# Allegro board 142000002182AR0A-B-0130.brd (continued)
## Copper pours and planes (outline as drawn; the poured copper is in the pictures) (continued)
VCC_12P_FAN4_IN on TOP (solid shape): 240.03,42.42 240.03,35.33 239.07,34.36 237.32,32.61 232.77,32.61 231.22,34.16 231.13,34.16 231.12,34.17 230.35,34.17 230.32,34.17 230.28,34.16 229.93,34.16 229.93,35.81 229.93,36.26 230.2,36.53 231.75,36.53 231.75,35.72 232.82,35.72 232.82,35.73 236.5,35.73 236.75,35.97 236.75,38.46 237.96,38.46 237.96,39.52 236.75,39.52 236.75,39.88 236.92,40.05 236.92,41.85 237.74,42.67 239.78,42.67
VCC_12P_FAN4_IN on BOTTOM: 237.44,55.32 237.52,55.4 238.89,55.4 238.99,55.3 238.99,47.32 239.32,46.99 239.32,42.24 239.95,41.61 239.95,38.93 239.57,38.55 236.48,38.55 235.79,39.24 235.79,44.3 236.7,45.21 236.7,46.66 237.44,47.4
VCC_12P_FAN4_OUT on TOP (solid shape): 243.75,45.48 244.23,45.48 244.52,45.39 244.82,45.48 245.63,45.48 245.97,45.14 245.97,43.46 245.99,43.44 245.99,43.34 246.09,43.34 247.04,42.39 247.04,37.82 245.49,36.27 245.49,36.19 245.48,36.18 245.48,35.41 245.48,35.37 245.49,35.33 245.49,34.99 243.84,34.99 243.84,34.99 243.04,34.99 242.77,35.26 242.77,36.8 243.55,36.8 243.55,37.87 243.21,37.87 243.21,38.05 243.33,38.18 243.79,38.18 243.84,38.23 243.84,39.5 243.84,40.26 243.84,41.53 243.84,41.58 243.54,41.88 243.55,41.88 243.55,42.95 241.59,42.95 241.59,42.93 241.07,42.93 240.49,43.51 240.49,45.49 240.89,45.9 243.33,45.9
VCC_12P_FAN4_OUT on BOTTOM: 239.7,43.35 239.7,47.01 239.99,47.29 239.99,55.23 240.15,55.4 241.43,55.4 241.52,55.3 241.52,47.32 242.27,46.58 242.27,45.85 243.1,45.01 244.9,45.01 245.51,44.41 245.51,41.52 244.94,40.95 242.1,40.95
VCC_12P_FAN5_IN on TOP: 302.96,38.57 304.88,38.57 306.36,40.05 308.38,40.05 308.71,39.72 308.71,37.72 306.52,35.53 306.52,32.49 305.79,31.77 305.79,31.5 305.71,31.42 305.71,30.21 305.59,30.08 303.96,30.08 303.94,30.1 302.56,30.1 302.1,30.55 302.1,32.07 302.3,32.27 303,32.27 303,37.36 303.09,37.45 303.09,38.44
VCC_12P_FAN5_IN on BOTTOM: 306.35,55.32 306.43,55.39 307.8,55.39 307.9,55.29 307.9,47.32 308.23,46.99 308.23,42.24 308.87,41.6 308.87,38.93 308.48,38.55 305.39,38.55 304.7,39.24 304.7,44.29 305.61,45.21 305.61,46.66 306.35,47.39
VCC_12P_FAN5_OUT on TOP: 313.79,31.31 313.79,30.03 313.55,29.78 312.41,29.78 311.87,30.32 311.87,38.18 311.88,38.19 309.7,40.38 309.7,42.69 310.12,43.11 314.09,43.11 314.49,42.71 314.49,40.95 315.7,39.74 315.7,32.56 314.64,31.49 313.97,31.49
VCC_12P_FAN5_OUT on BOTTOM: 308.61,43.34 308.61,47 308.9,47.29 308.9,55.23 309.06,55.39 310.34,55.39 310.43,55.3 310.43,47.32 311.18,46.57 311.18,45.84 312.01,45.01 313.81,45.01 314.42,44.4 314.42,41.52 313.85,40.95 311.01,40.95
VCC_12P_FAN6_IN on TOP: 371.73,39.24 373.38,39.24 374.65,40.51 375.54,40.51 375.92,40.13 375.92,35.69 374.22,33.99 374.22,32.46 374.14,32.38 371.73,32.38 371.09,33.02 371.09,33.27 371.13,33.3 371.66,33.3 371.73,33.37
VCC_12P_FAN6_IN on BOTTOM: 375.25,54.8 375.33,54.87 376.7,54.87 376.8,54.77 376.8,46.8 377.13,46.47 377.13,39.77 376.1,38.73 373.73,38.73 373.6,38.86 373.6,43.77 374.51,44.69 374.51,46.14 375.25,46.87
VCC_12P_FAN6_OUT on TOP: 380.75,43.31 383.03,43.31 383.54,42.8 383.54,41.78 385.95,39.37 385.95,36.7 384.05,34.8 384.05,33.78 383.79,33.53 382.27,33.53 381.38,34.42 381.38,40.39 380.87,40.89 380.49,40.89 380.24,41.15 380.24,42.8
VCC_12P_FAN6_OUT on BOTTOM: 377.51,42.82 377.51,46.48 377.8,46.77 377.8,54.71 377.96,54.87 379.24,54.87 379.33,54.78 379.33,46.8 380.08,46.05 380.08,45.32 380.91,44.49 382.71,44.49 383.32,43.88 383.32,41.71 383.02,41.41 378.92,41.41
VCC_CL_FAN1F on TOP (solid shape): 41.15,30 41.15,29.69 41.14,29.65 41.14,29.61 41.14,28.98 41.15,28.97 41.15,28.85 41.78,28.23 41.81,28.17 41.81,26.7 41.66,26.54 38.71,26.54 38.69,26.53 38.26,26.53 38.15,26.63 38.15,29.78 38.4,30.02 41.12,30.02
VCC_CL_FAN1R on TOP: 31.09,30.02 31.11,30 31.11,28.85 31.78,28.19 31.78,26.7 31.62,26.54 28.68,26.54 28.66,26.53 28.23,26.53 28.12,26.63 28.12,29.78 28.36,30.02
VCC_CL_FAN2F on TOP (solid shape): 108.46,31.9 108.46,31.6 108.45,31.56 108.45,31.52 108.45,30.88 108.46,30.87 108.46,30.76 109.09,30.13 109.12,30.08 109.12,28.26 108.78,27.92 105.7,27.92 105.46,28.16 105.46,31.68 105.71,31.93 108.43,31.93
VCC_CL_FAN2R on TOP (solid shape): 90.73,37.29 90.73,34.57 90.7,34.54 90.4,34.54 90.36,34.55 90.32,34.55 89.68,34.55 89.67,34.54 89.56,34.54 88.93,33.92 88.88,33.88 87.4,33.88 87.25,34.04 87.25,36.98 87.23,37 87.23,37.43 87.34,37.54 90.48,37.54
VCC_CL_FAN3F on TOP (solid shape): 179.32,30 179.32,29.69 179.32,29.65 179.32,29.61 179.32,28.98 179.32,28.97 179.32,28.85 179.95,28.23 179.98,28.17 179.98,26.7 179.83,26.54 176.89,26.54 176.87,26.53 176.44,26.53 176.33,26.63 176.33,29.78 176.57,30.02 179.3,30.02
VCC_CL_FAN3R on TOP (solid shape): 169.8,30 169.8,29.69 169.79,29.65 169.79,29.61 169.79,28.81 170.4,28.19 170.46,28.19 170.46,26.7 170.31,26.54 167.36,26.54 167.35,26.53 166.91,26.53 166.8,26.63 166.8,29.78 167.05,30.02 169.77,30.02
VCC_CL_FAN4F on TOP (solid shape): 245.49,32.79 245.49,32.49 245.48,32.45 245.48,32.41 245.48,31.77 245.49,31.76 245.49,31.65 245.8,31.34 245.8,29.24 244.96,28.4 242.67,28.4 242.53,28.54 242.53,29.08 242.57,29.08 242.57,30.61 242.5,30.61 242.5,32.57 242.74,32.82 245.47,32.82
VCC_CL_FAN4R on TOP (solid shape): 227.76,36.91 227.76,34.19 227.74,34.16 227.43,34.16 227.39,34.17 227.35,34.17 226.54,34.17 225.93,33.56 225.93,33.5 224.43,33.5 224.28,33.66 224.28,36.6 224.27,36.62 224.27,37.05 224.37,37.16 227.52,37.16
VCC_CL_FAN5F on TOP: 311.63,27.64 313.61,27.64 313.69,27.55 313.69,25.16 313.34,24.81 313.34,23.5 313.19,23.35 311.55,23.35 311.16,23.74 311.16,27.17
VCC_CL_FAN5R on TOP: 302.72,28.01 305.43,28.01 305.61,27.83 305.61,24.77 304.72,23.88 302.12,23.88 302.03,23.97 302.03,27.32
VCC_CL_FAN6F on TOP: 381.14,31.42 383.83,31.42 383.9,31.35 383.9,29.18 382.62,27.9 380.9,27.9 380.67,28.13 380.67,30.95
VCC_CL_FAN6R on TOP: 374.24,30.37 374.24,27.62 373.6,26.99 370.43,26.99 370.08,27.34 370.08,29.7 370.74,30.37
VDD3P3 on TOP (solid shape): 214.11,18.99 214.11,18.41 214.25,18.27 214.25,16.57 217.35,16.57 217.35,17.48 217.7,17.83 221.39,17.83 221.54,17.68 221.74,17.68 222.56,17.68 222.56,17.79 222.8,18.03 222.81,18.03 222.81,18.05 223.28,18.52 224.03,18.52 224.1,18.44 224.1,14.83 223.82,14.55 209.98,14.55 209.55,14.99 209.55,16.81 209.58,16.88 209.65,16.91 210.18,17.45 209.65,17.98 209.58,18.01 209.55,18.08 209.55,19.25 210.06,19.76 213.33,19.76
VDD3P3 on TOP: 109.5,21.2 112.57,21.2 114.68,19.09 114.68,17.06 113.24,17.06 109.43,20.87 109.43,21.14
VDD3P3 on TOP: 122.42,29.2 125.41,29.2 126.16,28.45 126.16,26.54 125.73,26.1 124.48,26.1 122.37,28.21 122.37,29.16
VDD3P3 on TOP: 147.34,10.92 154,10.92 154.35,10.58 154.35,8.49 153.96,8.1 149.48,8.1 147.25,10.33 147.25,10.83
VDD3P3 on TOP: 128.84,6.05 133.53,6.05 133.83,6.35 135.78,6.35 135.89,6.24 135.89,4.72 135.59,4.41 133.86,4.41 133.82,4.38 128.46,4.38 128.26,4.57 128.26,5.48
VDD3P3 on TOP: 201.78,21.69 204,21.69 204.18,21.52 204.18,19.68 204.17,19.67 202.01,19.67 201.63,20.05 201.63,21.54
VDD3P3 on TOP: 143.26,6.5 144.95,6.5 145.29,6.16 145.29,5.38 145.84,4.83 146.41,4.83 146.61,4.63 146.61,4.12 146.42,3.94 144.57,3.94 143.18,5.33 143.18,6.42
VDD3P3 on BOTTOM: 109.61,19.82 109.26,20.18 109.26,21.1 109.6,21.44 110.51,21.44 114.12,25.05 114.12,27.39 115.44,28.71 122.96,28.71 122.99,28.69 122.99,28.26 122.15,27.43 116.05,27.43 115.43,26.82 115.43,24.17 111.08,19.82
VDD3P3 on BOTTOM: 124.99,14.38 124.04,15.34 118.93,15.34 118.93,14.13 118.48,13.68 114.72,13.68 114.38,13.35 113.87,13.35 113.53,13.69 113.53,18.56 114.6,19.63 121.25,19.63 123.24,17.64 123.95,17.64 123.95,17.67 124.68,18.41 127.51,18.41 127.51,19.05 127.64,19.18 128.06,19.18 126.99,20.25 126.99,24.01 126.8,24.21 125.33,24.21 124.88,24.66 124.88,27.09 125.46,27.68 127.15,27.68 127.15,26.82 126.42,26.09 126.42,25.55 126.76,25.21 128.03,25.21 128.25,24.99 128.25,24.25 132.89,24.25 136,21.14 136,19.31 135.2,18.51 132.61,18.51 132.62,18.49 132.62,17.41 132.33,17.12 132.83,16.62 132.83,15.96 133.41,15.39 133.41,11.05 133.22,10.85 132.14,10.85 131.77,11.22 131.77,13.37 131.26,13.88 128.94,13.88 128.43,14.38
VDD3P3 on BOTTOM: 204.28,21.39 204.28,20 203.88,19.6 191.35,19.6 190.7,20.25 171.2,20.25 170.26,21.19 170.26,22.25 171.07,23.06 190.35,23.06 190.38,23.03 202.65,23.03
(no net) on TOP: 177.77,25.86 179.58,25.86 179.83,25.6 179.83,23.88 179.45,23.5 175.01,23.5 174.75,23.75 174.75,25.86 174.88,25.98 177.65,25.98
(no net) on TOP: 217.22,23.09 217.35,22.96 217.35,22.38 217.27,22.3 215.69,22.3 214.17,20.78 207.26,20.78 207.09,20.95 207.09,21.69 206.43,21.69 206.25,21.87 206.25,22.99 206.35,23.09
(no net) on TOP: 42.7,36.99 42.7,35.03 41.15,33.48 41.15,32.18 41.12,32.16 39.78,32.16 39.74,32.19 39.05,32.19 38.79,32.46 38.79,34.72 39.5,35.43 39.5,38.72 39.17,39.05 37.64,39.05 37.28,39.42 35.94,39.42 34.98,40.39 34.98,44.28 35.2,44.5 38.89,44.5 39.27,44.12 39.27,42.99 39.68,42.58 40.33,42.58 40.61,42.3 40.91,42.3 42.73,40.48 42.73,37.02
(no net) on TOP: 245.47,32.82 245.49,32.79 245.49,31.65 245.8,31.34 245.8,29.24 244.96,28.4 242.67,28.4 242.53,28.54 242.53,29.02 242.5,29.05 242.5,32.57 242.74,32.82
(no net) on TOP: 90.73,34.57 90.7,34.54 89.56,34.54 88.9,33.88 87.4,33.88 87.25,34.04 87.25,36.98 87.23,37 87.23,37.43 87.34,37.54 90.48,37.54 90.73,37.29
(no net) on TOP: 227.76,34.19 227.74,34.16 226.59,34.16 225.93,33.5 224.43,33.5 224.28,33.66 224.28,36.6 224.27,36.62 224.27,37.05 224.37,37.16 227.52,37.16 227.76,36.91
(no net) on TOP: 247.04,42.39 247.04,37.82 245.49,36.27 245.49,34.98 245.47,34.95 244.12,34.95 244.08,34.99 243.04,34.99 242.77,35.26 242.77,37.62 243.33,38.18 243.79,38.18 243.84,38.23 243.84,41.58 242.52,42.9 241.1,42.9 240.49,43.51 240.49,45.49 240.89,45.9 243.33,45.9 243.75,45.48 245.63,45.48 245.97,45.14 245.97,43.46
(no net) on TOP: 97.49,32.99 95.73,32.99 94.18,34.54 92.89,34.54 92.86,34.57 92.86,35.92 92.9,35.95 92.9,36.64 93.17,36.91 95.43,36.91 96.14,36.2 99.43,36.2 99.85,36.62 99.85,39.21 99.3,39.77 99.3,42.1 100.14,42.94 102.69,42.94 103.17,42.45 103.17,35.97 99.71,32.51 97.97,32.51
(no net) on TOP: 99.44,38.11 99.44,37.08 99.31,36.96 96.01,36.96 95.76,37.21 93.05,37.21 92.62,36.78 92.62,31.17 92.06,30.61 88.33,30.61 88.05,30.89 88.05,31.42 88.15,31.52 88.72,31.52 88.74,31.5 88.74,31.44 88.97,31.21 90.17,31.21 90.42,31.46 90.42,32.16 90.98,32.72 90.98,37.34 90.53,37.8 87.27,37.8 87.17,37.9 87.17,38.86 87.43,39.12 98.43,39.12
(no net) on TOP: 215.69,21.69 217.55,21.69 217.88,22.02 217.88,26.14 217.15,26.87 216.5,26.87 215.73,27.64 214.61,27.64 213.41,26.43 212.74,26.43 212.45,26.72 209.75,26.72 209.7,26.77 209.7,28.96 210.95,30.2 219.3,30.2 220.32,29.18 220.32,21.18 220.91,20.59 222.45,20.59 222.72,20.32 222.72,18.38 222.59,18.24 221.72,18.24 221.19,18.77 217.66,18.77 217.31,18.42 214.46,18.42 214.36,18.52 214.36,20.36 215.58,21.58
(no net) on TOP: 232.16,31.75 232.16,29.97 233.43,28.7 235.33,28.7 235.56,28.93 235.56,31.85 235.41,32 232.41,32
(no net) on TOP: 180.87,35.03 179.32,33.48 179.32,32.18 179.3,32.16 177.95,32.16 177.91,32.19 177.23,32.19 176.96,32.46 176.96,34.72 177.67,35.43 177.67,38.63 177.22,39.09 175.81,39.09 175.39,39.52 173,39.52 172.67,39.85 172.67,43.64 173.08,44.04 176.02,44.04 177.01,43.05 178.31,43.05 180.87,40.49
(no net) on TOP: 104.63,40.64 105.92,40.64 106.05,40.51 106.05,37.21 105.79,36.96 105.79,34.25 106.22,33.82 112.22,33.82 112.6,33.44 112.6,29.47 112.38,29.25 111.58,29.25 111.48,29.35 111.48,29.92 111.5,29.94 111.57,29.94 111.8,30.17 111.8,31.37 111.55,31.62 110.84,31.62 110.28,32.18 105.52,32.18 104.61,31.27 103.4,31.27 103.28,31.39 103.28,33.99 103.67,34.38 103.67,40.98 103.68,40.99 104.42,40.99 104.46,40.94 104.46,40.81
(no net) on TOP: 223.28,18.52 224.03,18.52 224.1,18.44 224.1,14.83 223.82,14.55 209.98,14.55 209.55,14.99 209.55,19.25 210.06,19.76 213.33,19.76 214.27,18.82 214.27,17.42 217.3,17.42 217.7,17.83 221.39,17.83 221.54,17.68 222.44,17.68
(no net) on TOP: 37.74,38.73 38.61,38.73 38.73,38.61 38.73,35.31 38.48,35.05 38.48,32.34 38.91,31.91 44.52,31.91 45.29,31.15 45.29,27.56 45.07,27.34 44.27,27.34 44.17,27.45 44.17,28.02 44.19,28.04 44.26,28.04 44.49,28.27 44.49,29.46 44.24,29.71 43.53,29.71 42.97,30.28 38.35,30.28 37.9,29.82 37.9,26.57 37.8,26.47 36.83,26.47 36.58,26.72 36.58,33.32 36.25,33.66 36.25,38.89 36.42,39.07 37.41,39.07
(no net) on TOP: 167.39,38.61 167.39,35.31 167.13,35.05 167.13,32.34 167.56,31.91 173.18,31.91 173.74,31.35 173.74,27.46 173.58,27.3 172.09,27.3 171.98,27.41 171.98,27.92 172.1,28.04 172.91,28.04 173.14,28.27 173.14,29.46 172.89,29.71 172.19,29.71 171.62,30.28 167,30.28 166.55,29.82 166.55,26.57 166.45,26.47 165.48,26.47 165.23,26.72 165.23,38.7 165.88,39.35 166.77,39.35 167.01,39.58 167.71,39.58 167.83,39.46 167.83,38.98 167.67,38.82 167.6,38.82
(no net) on TOP: 39.6,25.86 41.4,25.86 41.66,25.6 41.66,23.88 41.27,23.5 36.83,23.5 36.58,23.75 36.58,25.86 36.7,25.98 39.47,25.98
(no net) on TOP: 110.87,36.32 113.33,36.32 113.72,36.7 113.72,39.57 112.47,40.82 110.87,40.82 110.62,40.56 110.62,36.58
(no net) on TOP: 247.9,37.21 249.68,37.21 249.94,37.47 249.94,39.88 248.95,40.87 248.95,42.21 248.82,42.34 247.88,42.34 247.65,42.11 247.65,37.47
(no net) on TOP: 43.56,34.42 45.34,34.42 45.59,34.67 45.59,37.08 45.47,37.21 43.43,37.21 43.31,37.08 43.31,34.67
(no net) on TOP: 168.25,25.86 170.05,25.86 170.31,25.6 170.31,23.17 169.98,22.84 165.84,22.84 165.23,23.45 165.23,25.86 165.35,25.98 168.12,25.98
(no net) on TOP: 232.77,32.61 231.22,34.16 229.92,34.16 229.9,34.19 229.9,35.53 229.93,35.57 229.93,36.26 230.2,36.53 232.12,36.53 232.12,36.38 232.77,35.73 236.5,35.73 236.75,35.97 236.75,41.7 237.72,42.67 239.78,42.67 240.03,42.42 240.03,35.33 239.07,34.36 237.32,32.61
(no net) on TOP: 86.56,36.09 86.56,34.29 86.31,34.04 84.58,34.04 84.2,34.42 84.2,38.86 84.45,39.12 86.56,39.12 86.69,38.99 86.69,36.22
(no net) on TOP: 172.21,34.42 173.99,34.42 174.24,34.67 174.24,37.08 174.12,37.21 172.09,37.21 171.96,37.08 171.96,34.67
(no net) on TOP: 215.73,24.61 217.17,24.61 217.35,24.43 217.35,23.7 217.3,23.65 209.09,23.65 208.74,24 208.74,25.3 209.05,25.62 213.05,25.62 213.12,25.55 213.12,25.1 213.55,24.67 215.67,24.67
(no net) on TOP: 41.12,30.02 41.15,30 41.15,28.85 41.81,28.19 41.81,26.7 41.66,26.54 38.71,26.54 38.69,26.53 38.26,26.53 38.15,26.63 38.15,29.78 38.4,30.02
(no net) on TOP: 110.01,36.93 108.46,35.38 108.46,34.09 108.43,34.06 107.09,34.06 107.05,34.1 106.36,34.1 106.1,34.37 106.1,36.63 106.81,37.34 106.81,40.75 106.64,40.91 105.81,40.91 104.86,41.87 104.79,41.87 102.75,43.9 102.75,45.45 103.44,46.15 105.64,46.15 106.35,45.43 107.59,45.43 108.2,44.83 108.2,43.64 108.56,43.28 109.53,43.28 110.01,42.81
(no net) on TOP: 181.74,34.42 183.51,34.42 183.77,34.67 183.77,38.28 183.01,39.04 181.51,39.04 181.36,38.89 181.36,37.08 181.48,36.96 181.48,34.67
(no net) on TOP: 171.35,36.96 171.35,35.03 169.8,33.48 169.8,32.18 169.77,32.16 168.43,32.16 168.39,32.19 167.7,32.19 167.44,32.46 167.44,34.72 168.15,35.43 168.15,38.7 168.59,39.14 168.84,39.14 168.96,39.26 168.96,40.08 168.38,40.66 168.38,42.32 169.44,43.38 171.37,43.38 172.29,42.47 172.29,37.9
(no net) on TOP: 223.6,35.71 223.6,34.21 223.49,34.11 220.88,34.11 220.62,34.37 220.62,38.1 221.26,38.73 223.6,38.73 223.72,38.61 223.72,35.84
(no net) on TOP: 95.12,32.13 95.12,30.35 95.38,30.1 97.79,30.1 97.92,30.23 97.92,31.93 97.46,32.38 95.38,32.38
(no net) on TOP: 236.47,38.48 236.47,36.7 236.35,36.58 233.04,36.58 232.79,36.83 230.08,36.83 229.65,36.4 229.65,30.79 229.04,30.18 225.35,30.18 225.15,30.37 225.15,31.02 225.26,31.13 225.7,31.13 226,30.83 227.2,30.83 227.45,31.07 227.45,31.78 228.02,32.34 228.02,36.96 227.56,37.41 224.31,37.41 224.21,37.52 224.21,38.48 224.46,38.73 236.22,38.73
(no net) on TOP: 108.43,31.93 108.46,31.9 108.46,30.76 109.12,30.1 109.12,28.26 108.78,27.92 105.7,27.92 105.46,28.16 105.46,31.68 105.71,31.93
(no net) on TOP: 169.77,30.02 169.8,30 169.8,28.85 170.46,28.19 170.46,26.7 170.31,26.54 167.36,26.54 167.35,26.53 166.91,26.53 166.8,26.63 166.8,29.78 167.05,30.02
(no net) on TOP: 179.3,30.02 179.32,30 179.32,28.85 179.98,28.19 179.98,26.7 179.83,26.54 176.89,26.54 176.87,26.53 176.44,26.53 176.33,26.63 176.33,29.78 176.57,30.02
BS_VDD3P3 on TOP: 217.35,25.82 217.35,25.02 217.32,24.99 214.07,24.99 214.06,25.01 214.06,25.77 214.11,25.82 215.33,25.82 215.85,26.34 216.83,26.34
FAN_12V on TOP (solid shape): 97.46,32.38 97.92,31.93 97.92,30.23 97.79,30.1 95.38,30.1 95.12,30.35 95.12,32.13 95.38,32.38 96.01,32.38
FAN_12V on TOP (solid shape): 113.72,39.57 113.72,36.7 113.33,36.32 110.87,36.32 110.62,36.58 110.62,37.21 110.62,37.21 110.62,38.74 110.62,38.74 110.62,40.56 110.87,40.82 112.47,40.82
FAN_12V on TOP (solid shape): 174.24,37.08 174.24,34.67 173.99,34.42 172.21,34.42 171.96,34.67 171.96,35.31 171.96,36.83 171.96,37.08 172.09,37.21 174.12,37.21
FAN_12V on TOP (solid shape): 234.57,32 235.41,32 235.56,31.85 235.56,28.93 235.33,28.7 233.43,28.7 232.16,29.97 232.16,31.75 232.41,32 233.04,32
FAN_12V on TOP (solid shape): 45.01,37.21 45.47,37.21 45.59,37.08 45.59,34.67 45.34,34.42 43.56,34.42 43.31,34.67 43.31,35.31 43.31,36.83 43.31,37.08 43.43,37.21 45.01,37.21
FAN_12V on TOP (solid shape): 86.69,38.99 86.69,38.76 85.89,38.76 85.89,37.69 86.69,37.69 86.69,36.22 86.56,36.09 86.56,34.29 86.31,34.04 84.58,34.04 84.2,34.42 84.2,38.86 84.45,39.12 86.56,39.12
FAN_12V on TOP (solid shape): 165.58,25.18 166.65,25.18 166.65,25.98 168.12,25.98 168.25,25.86 170.05,25.86 170.31,25.6 170.31,23.17 169.98,22.84 165.84,22.84 165.23,23.45 165.23,25.86 165.35,25.98 165.58,25.98
FAN_12V on TOP (solid shape): 175.11,25.18 176.17,25.18 176.17,25.98 177.65,25.98 177.77,25.86 179.58,25.86 179.83,25.6 179.83,23.91 179.42,23.5 175.01,23.5 174.75,23.75 174.75,25.86 174.88,25.98 175.11,25.98
FAN_12V on TOP (solid shape): 183.77,38.28 183.77,34.67 183.51,34.42 181.74,34.42 181.48,34.67 181.48,35.31 181.48,36.83 181.48,36.96 181.36,37.08 181.36,38.89 181.51,39.04 183.01,39.04
FAN_12V on TOP (solid shape): 211.58,24.9 213.31,24.9 213.55,24.67 215.67,24.67 215.73,24.61 217.17,24.61 217.35,24.43 217.35,23.7 217.3,23.65 209.09,23.65 208.74,24 208.74,25.3 209.05,25.62 211.58,25.62
FAN_12V on TOP (solid shape): 248.95,42.21 248.95,40.87 249.94,39.88 249.94,37.47 249.68,37.21 247.9,37.21 247.65,37.47 247.65,38.1 247.65,39.62 247.65,42.11 247.88,42.34 248.82,42.34
FAN_12V on TOP (solid shape): 223.72,38.61 223.72,38.38 222.92,38.38 222.92,37.31 223.72,37.31 223.72,35.94 223.65,35.94 223.65,35.76 223.6,35.71 223.6,34.21 223.49,34.11 220.88,34.11 220.62,34.37 220.62,38.1 221.26,38.73 223.6,38.73
FAN_12V on TOP (solid shape): 36.93,25.18 38,25.18 38,25.98 39.47,25.98 39.6,25.86 41.4,25.86 41.66,25.6 41.66,23.88 41.27,23.5 37.57,23.5 37.38,23.54 37.18,23.52 37.17,23.52 36.8,23.52 36.58,23.75 36.58,25.86 36.7,25.98 36.93,25.98
FAN_12V on TOP: 33.53,34.42 35.31,34.42 35.56,34.67 35.56,37.08 35.43,37.21 33.71,37.21 33.27,36.78 33.27,34.67
FAN_12V on TOP: 368.68,30.27 369.3,29.65 369.3,4 368.24,2.93 361.61,2.93 358.26,6.29 358.26,28.44 360.09,30.27
FAN_12V on TOP: 101.63,30.99 104.52,30.99 104.85,30.66 104.85,27.84 104.57,27.56 101.8,27.56 101.32,28.04 101.32,30.68
FAN_12V on TOP: 378.98,27.34 382.29,27.34 382.34,27.29 382.34,25.52 381.76,24.95 381.75,24.95 381.5,24.7 378.79,24.7 378.48,25 378.48,26.85
FAN_12V on TOP: 311.4,22.61 313.56,22.61 313.69,22.73 315.21,22.73 315.34,22.61 315.34,20.57 314.83,20.07 311.53,20.07 311.28,20.32 311.28,22.48
FAN_12V on TOP: 308.86,32.89 308.61,32.64 307.09,32.64 306.96,32.77 306.96,35.8 307.93,36.77 308.56,36.77 308.86,36.46
FAN_12V on TOP: 303.02,23.11 306.58,23.11 306.7,22.99 306.7,20.95 305.94,20.19 303.4,20.19 302.77,20.83 302.77,22.86
FAN_12V on TOP: 241.99,28.57 241.78,28.37 237.85,28.37 237.64,28.58 237.64,31.62 237.87,31.85 241.71,31.85 241.99,31.57
FAN_12V on TOP: 385.95,14.22 387.86,14.22 389.13,15.49 390.91,15.49 391.16,15.24 391.16,11.56 393,9.72 394.91,9.72 395.22,9.4 395.22,6.22 394.46,5.46 393.32,5.46 393.19,5.33 381.13,5.33 380.75,5.71 380.75,9.78 381.25,10.29 385.7,10.29 385.83,10.41 385.83,14.1
FAN_12V on TOP: 316.47,35.86 318.65,35.86 319.12,35.38 319.12,32.47 318.76,32.1 316.64,32.1 316.13,32.61 316.13,35.51
FAN_12V on TOP: 386.84,40.39 389,40.39 390.02,39.37 390.02,37.47 389.38,36.83 386.97,36.83 386.59,37.21 386.59,40.13
FAN_12V on TOP: 378.2,38.94 378.2,37.35 378.08,37.23 378.08,36.57 378.32,36.33 378.32,35.38 378.06,35.12 376.87,35.12 376.57,35.42 376.57,36.47 376.74,36.63 376.74,38.37 376.58,38.52 376.58,39.03 376.72,39.16 377.98,39.16
FAN_12V on TOP: 29.57,25.86 31.37,25.86 31.62,25.6 31.62,23.88 31.24,23.5 26.8,23.5 26.54,23.75 26.54,25.86 26.67,25.98 29.44,25.98
FAN_12V on BOTTOM: 95.25,32.26 97.92,32.26 98.17,32 98.17,30.23 97.92,29.97 95.38,29.97 95.12,30.23 95.12,32.13
FAN_12V on BOTTOM: 238.25,31.62 240.16,31.62 240.66,31.11 240.66,29.46 240.16,28.96 238.25,28.96 238,29.21 238,31.37
FAN_12V on BOTTOM: 165.74,26.04 167.64,26.04 168.02,25.65 168.02,23.75 167.77,23.5 165.48,23.5 165.23,23.75 165.23,25.53
FAN_12V on BOTTOM: 26.92,23.62 38.81,23.62 39.09,23.9 39.09,25.91 38.71,26.29 27.69,26.29 26.67,25.27 26.67,23.88
FAN_12V on BOTTOM: 376.96,8.24 389.2,8.24 389.66,7.78 389.66,3.11 388.97,2.42 365.15,2.42 363.97,3.6 363.97,8 364.44,8.46 376.73,8.46
FAN_12V on V3: 376.96,8.24 389.2,8.24 389.66,7.78 389.66,3.11 388.97,2.42 380.51,2.42 379.84,3.09 378.8,3.09 378.4,3.49 377.37,3.49 376.97,3.09 364.48,3.09 363.97,3.6 363.97,8 364.44,8.46 376.73,8.46
FAN_12V on V3: outline of 195 points within 26.54,20.07 389.8,41.02
FAN_12V_PDU on TOP: 398.91,20.95 405.89,20.95 406.65,20.19 406.65,11.05 405.76,10.16 393.06,10.16 391.54,11.68 391.54,24.05 391.54,24.05 395.81,24.05
FAN_12V_PDU on BOTTOM: 391.8,23.88 395.99,23.88 398.91,20.95 405.89,20.95 406.65,20.19 406.65,11.05 405.76,10.16 393.06,10.16 391.54,11.68 391.54,23.62
HS_MOS_D on TOP, BOTTOM: 389.76,16.33 389.68,16.25 389.13,16.25 389.13,16.26 386.33,16.26 385.83,15.75 385.83,14.61 385.55,14.34 385.55,10.78 385.44,10.67 380.75,10.67 380.11,11.3 380.11,13.93 380.56,14.38 380.56,15.61 380.71,15.76 380.71,19.31 385.56,24.15 389.71,24.15 389.76,24.1
SW_VDD3P3 on TOP (solid shape): 217.35,22.96 217.35,22.38 217.27,22.3 215.69,22.3 214.17,20.78 207.26,20.78 207.16,20.88 207.16,22.31 206.25,22.31 206.25,22.99 206.35,23.09 217.22,23.09

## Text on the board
User.Comments: CR_UNNAMED_7 | CR_UNNAMED_1 | CR_UNNAMED_8 | CR_UNNAMED_2 | CR_UNNAMED_5 | CR_UNNAMED_4 | CR_UNNAMED_6 | STB V2
Ref Des/Silkscreen Top: P/N:142000002182A REV:0A
User.9: TOP (COMPONENT_SIDE)                      1
User.10: G2  (GND_LAYER_2)                         2
User.11: V3  (VCC_LAYER_3)                         3
User.12: BOT (SOLDER_SIDE)                         4
User.13: SST (SILKSCREEN_TOP)                      5
User.14: SSB (SILKSCREEN_BOTTOM)                   6
User.15: SMT (SOLDER_MASK_TOP)                     7
User.16: SMB (SOLDER_MASK_BOTTOM)                   8
User.17: DRILL(FINISH HOLE SIZE LIST)               9
User.18: PMT (PASTE_MASK_TOP)                     10
User.19: PMB (PASTE_MASK_BOTTOM)                  11
User.20: DIM (BOARD_DIMENSION)                    12
User.21: FIGURE | SIZE | 10.0 | 12.0 | 40.0 | 67.0 | 118.0 | 125.0 | 138.0 | TOLERANCE | +3.0/-3.0 | +2.0/-2.0 | +3.0/-0.0 | ALL UNITS ARE IN MILS | PLATED | NON-PLATED | QTY | 97 | 1624 | 4 | 2 | 3 | 8 | DRILL CHART: TOP to BOTTOM
User.24: C144 | C145 | C147 | C150 | C153 | C156 | C159 | C157 | C163 | C164 | R170 | C143 | C146 | C148 | C151 | C149 | C152 | C155 | C154 | C158 | C161 | C160 | C162 | R171
User.29: Excess check:Jul 24 10:43:07 2018 | XY-Check acute:Jul 24 10:43:48 2018 | XY-Check rotation:Aug 08 11:57:33 2018 | XY-Check txt overlap:Aug 08 11:56:33 2018 | XY-Excess check:Jul 24 10:43:07 2018 | XY-Norefdes:Aug 08 11:56:55 2018 | check acute:Jul 24 10:43:48 2018 | check rotation:Aug 08 11:57:33 2018 | check txt overlap:Aug 08 11:56:33 2018 | norefdes:Aug 08 11:56:55 2018
